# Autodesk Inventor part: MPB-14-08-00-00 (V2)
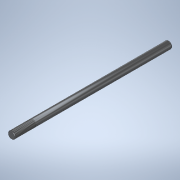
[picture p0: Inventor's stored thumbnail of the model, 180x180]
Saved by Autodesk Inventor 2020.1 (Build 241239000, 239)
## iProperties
Created: 2020-04
Part Number: MPB-14-08-00-00 (V2)
Material: CK55
Document SubType Name: Modeling
Designer: Safarabadi
Density: 7.85 g/cm^3
Appearance: CK55
Author: Safarabadi
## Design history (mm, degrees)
derived "MPB-14-08-00-00.ipt"
feature "Solid1::MPB-14-08-00-00.ipt" dims "d0" = 10
tag "TaggingFeature1"
body "Solid1"
